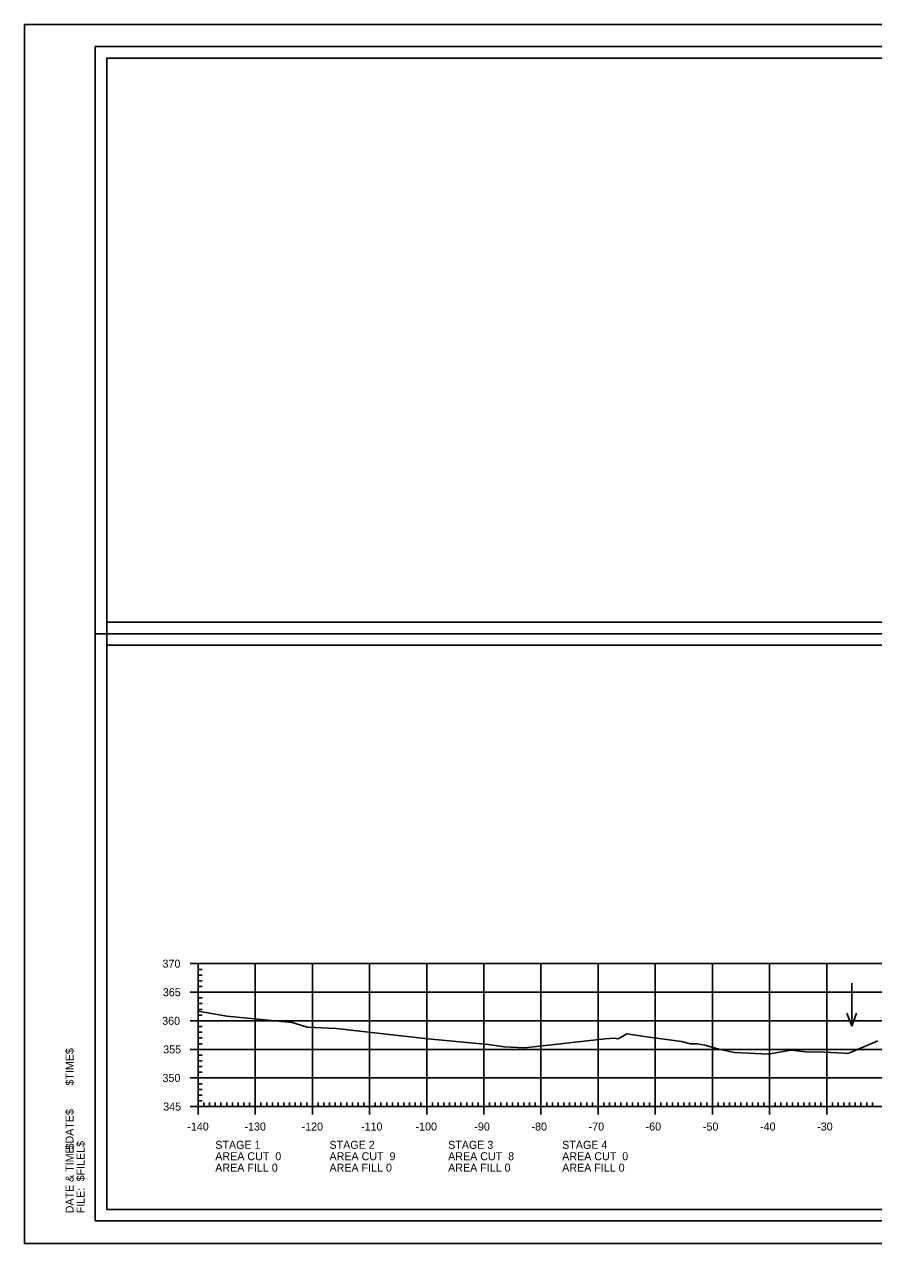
# Model space of a CAD drawing. Extents: x 1368910 to 1369601, y 380116 to 380950.
# Drawn here: x 1369267.2 to 1369415.8, y 380737.1 to 380950.5 of the extents above; entities that cross this region are included whole.
import ezdxf

# ---------------------------------------------------------------- set-up
doc = ezdxf.new("R2010")
doc.units = 0
for name, color, linetype in [('R_Axis', 7, 'Continuous'), ('R_Axis Annot', 7, 'Continuous'), ('R_Border', 7, 'Continuous'), ('R_Border Notes', 7, 'Continuous'), ('R_Border Plan-Plan', 7, 'Continuous'), ('R_Exist Surface', 7, 'Continuous'), ('R_Grid', 7, 'Continuous'), ('R_No Plot', 7, 'Continuous'), ('R_Water Annot', 7, 'Continuous')]:
    doc.layers.add(name, color=color, linetype=linetype)

msp = doc.modelspace()

# ---------------------------------------------------------------- linework, layer by layer
at = {"layer": 'R_Axis'}
for p, q in [((1369296.19, 380786.1), (1369298.99, 380786.1)), ((1369297.59, 380761.1), (1369297.59, 380786.1)), ((1369297.59, 380785.1), (1369298.29, 380785.1)), ((1369297.59, 380784.1), (1369298.29, 380784.1)), ((1369297.59, 380783.1), (1369298.29, 380783.1)), ((1369297.59, 380782.1), (1369298.29, 380782.1)), ((1369296.19, 380781.1), (1369298.99, 380781.1)), ((1369297.59, 380780.1), (1369298.29, 380780.1)), ((1369297.59, 380779.1), (1369298.29, 380779.1)), ((1369297.59, 380778.1), (1369298.29, 380778.1)), ((1369296.19, 380776.1), (1369298.99, 380776.1)), ((1369297.59, 380777.1), (1369298.29, 380777.1)), ((1369297.59, 380775.1), (1369298.29, 380775.1)), ((1369297.59, 380774.1), (1369298.29, 380774.1)), ((1369297.59, 380773.1), (1369298.29, 380773.1)), ((1369297.59, 380772.1), (1369298.29, 380772.1)), ((1369296.19, 380771.1), (1369298.99, 380771.1)), ((1369297.59, 380770.1), (1369298.29, 380770.1)), ((1369297.59, 380769.1), (1369298.29, 380769.1)), ((1369297.59, 380768.1), (1369298.29, 380768.1)), ((1369297.59, 380767.1), (1369298.29, 380767.1)), ((1369296.19, 380766.1), (1369298.99, 380766.1)), ((1369297.59, 380765.1), (1369298.29, 380765.1)), ((1369297.59, 380764.1), (1369298.29, 380764.1)), ((1369297.59, 380763.1), (1369298.29, 380763.1)), ((1369296.19, 380761.1), (1369298.99, 380761.1)), ((1369297.59, 380759.7), (1369297.59, 380762.5)), ((1369297.59, 380762.1), (1369298.29, 380762.1)), ((1369297.59, 380761.1), (1369577.59, 380761.1)), ((1369298.59, 380761.1), (1369298.59, 380761.8)), ((1369299.59, 380761.1), (1369299.59, 380761.8)), ((1369300.59, 380761.1), (1369300.59, 380761.8)), ((1369301.59, 380761.1), (1369301.59, 380761.8)), ((1369302.59, 380761.1), (1369302.59, 380761.8)), ((1369303.59, 380761.1), (1369303.59, 380761.8)), ((1369304.59, 380761.1), (1369304.59, 380761.8)), ((1369305.59, 380761.1), (1369305.59, 380761.8)), ((1369306.59, 380761.1), (1369306.59, 380761.8)), ((1369307.59, 380759.7), (1369307.59, 380762.5)), ((1369308.59, 380761.1), (1369308.59, 380761.8)), ((1369309.59, 380761.1), (1369309.59, 380761.8)), ((1369310.59, 380761.1), (1369310.59, 380761.8)), ((1369311.59, 380761.1), (1369311.59, 380761.8)), ((1369312.59, 380761.1), (1369312.59, 380761.8)), ((1369313.59, 380761.1), (1369313.59, 380761.8)), ((1369314.59, 380761.1), (1369314.59, 380761.8)), ((1369315.59, 380761.1), (1369315.59, 380761.8)), ((1369316.59, 380761.1), (1369316.59, 380761.8)), ((1369317.59, 380759.7), (1369317.59, 380762.5)), ((1369318.59, 380761.1), (1369318.59, 380761.8)), ((1369319.59, 380761.1), (1369319.59, 380761.8)), ((1369320.59, 380761.1), (1369320.59, 380761.8)), ((1369321.59, 380761.1), (1369321.59, 380761.8)), ((1369322.59, 380761.1), (1369322.59, 380761.8)), ((1369323.59, 380761.1), (1369323.59, 380761.8)), ((1369324.59, 380761.1), (1369324.59, 380761.8)), ((1369325.59, 380761.1), (1369325.59, 380761.8)), ((1369326.59, 380761.1), (1369326.59, 380761.8)), ((1369327.59, 380759.7), (1369327.59, 380762.5)), ((1369328.59, 380761.1), (1369328.59, 380761.8)), ((1369329.59, 380761.1), (1369329.59, 380761.8)), ((1369330.59, 380761.1), (1369330.59, 380761.8)), ((1369331.59, 380761.1), (1369331.59, 380761.8)), ((1369332.59, 380761.1), (1369332.59, 380761.8)), ((1369333.59, 380761.1), (1369333.59, 380761.8)), ((1369334.59, 380761.1), (1369334.59, 380761.8)), ((1369335.59, 380761.1), (1369335.59, 380761.8)), ((1369336.59, 380761.1), (1369336.59, 380761.8)), ((1369337.59, 380759.7), (1369337.59, 380762.5)), ((1369338.59, 380761.1), (1369338.59, 380761.8)), ((1369339.59, 380761.1), (1369339.59, 380761.8)), ((1369340.59, 380761.1), (1369340.59, 380761.8)), ((1369341.59, 380761.1), (1369341.59, 380761.8)), ((1369342.59, 380761.1), (1369342.59, 380761.8)), ((1369343.59, 380761.1), (1369343.59, 380761.8)), ((1369344.59, 380761.1), (1369344.59, 380761.8)), ((1369345.59, 380761.1), (1369345.59, 380761.8)), ((1369346.59, 380761.1), (1369346.59, 380761.8)), ((1369347.59, 380759.7), (1369347.59, 380762.5)), ((1369348.59, 380761.1), (1369348.59, 380761.8)), ((1369349.59, 380761.1), (1369349.59, 380761.8)), ((1369350.59, 380761.1), (1369350.59, 380761.8)), ((1369351.59, 380761.1), (1369351.59, 380761.8)), ((1369352.59, 380761.1), (1369352.59, 380761.8)), ((1369353.59, 380761.1), (1369353.59, 380761.8)), ((1369354.59, 380761.1), (1369354.59, 380761.8)), ((1369355.59, 380761.1), (1369355.59, 380761.8)), ((1369356.59, 380761.1), (1369356.59, 380761.8)), ((1369357.59, 380759.7), (1369357.59, 380762.5)), ((1369358.59, 380761.1), (1369358.59, 380761.8)), ((1369359.59, 380761.1), (1369359.59, 380761.8)), ((1369360.59, 380761.1), (1369360.59, 380761.8)), ((1369361.59, 380761.1), (1369361.59, 380761.8)), ((1369362.59, 380761.1), (1369362.59, 380761.8)), ((1369363.59, 380761.1), (1369363.59, 380761.8)), ((1369364.59, 380761.1), (1369364.59, 380761.8)), ((1369365.59, 380761.1), (1369365.59, 380761.8)), ((1369366.59, 380761.1), (1369366.59, 380761.8)), ((1369367.59, 380759.7), (1369367.59, 380762.5)), ((1369368.59, 380761.1), (1369368.59, 380761.8)), ((1369369.59, 380761.1), (1369369.59, 380761.8)), ((1369370.59, 380761.1), (1369370.59, 380761.8)), ((1369371.59, 380761.1), (1369371.59, 380761.8)), ((1369372.59, 380761.1), (1369372.59, 380761.8)), ((1369373.59, 380761.1), (1369373.59, 380761.8)), ((1369374.59, 380761.1), (1369374.59, 380761.8)), ((1369375.59, 380761.1), (1369375.59, 380761.8)), ((1369376.59, 380761.1), (1369376.59, 380761.8)), ((1369377.59, 380759.7), (1369377.59, 380762.5)), ((1369378.59, 380761.1), (1369378.59, 380761.8)), ((1369379.59, 380761.1), (1369379.59, 380761.8)), ((1369380.59, 380761.1), (1369380.59, 380761.8)), ((1369381.59, 380761.1), (1369381.59, 380761.8)), ((1369382.59, 380761.1), (1369382.59, 380761.8)), ((1369383.59, 380761.1), (1369383.59, 380761.8)), ((1369384.59, 380761.1), (1369384.59, 380761.8)), ((1369385.59, 380761.1), (1369385.59, 380761.8)), ((1369386.59, 380761.1), (1369386.59, 380761.8)), ((1369387.59, 380759.7), (1369387.59, 380762.5)), ((1369388.59, 380761.1), (1369388.59, 380761.8)), ((1369389.59, 380761.1), (1369389.59, 380761.8)), ((1369390.59, 380761.1), (1369390.59, 380761.8)), ((1369391.59, 380761.1), (1369391.59, 380761.8)), ((1369392.59, 380761.1), (1369392.59, 380761.8)), ((1369393.59, 380761.1), (1369393.59, 380761.8)), ((1369394.59, 380761.1), (1369394.59, 380761.8)), ((1369395.59, 380761.1), (1369395.59, 380761.8)), ((1369396.59, 380761.1), (1369396.59, 380761.8)), ((1369397.59, 380759.7), (1369397.59, 380762.5)), ((1369398.59, 380761.1), (1369398.59, 380761.8)), ((1369399.59, 380761.1), (1369399.59, 380761.8)), ((1369400.59, 380761.1), (1369400.59, 380761.8)), ((1369401.59, 380761.1), (1369401.59, 380761.8)), ((1369402.59, 380761.1), (1369402.59, 380761.8)), ((1369403.59, 380761.1), (1369403.59, 380761.8)), ((1369404.59, 380761.1), (1369404.59, 380761.8)), ((1369405.59, 380761.1), (1369405.59, 380761.8)), ((1369406.59, 380761.1), (1369406.59, 380761.8)), ((1369407.59, 380759.7), (1369407.59, 380762.5)), ((1369408.59, 380761.1), (1369408.59, 380761.8)), ((1369409.59, 380761.1), (1369409.59, 380761.8)), ((1369410.59, 380761.1), (1369410.59, 380761.8)), ((1369411.59, 380761.1), (1369411.59, 380761.8)), ((1369412.59, 380761.1), (1369412.59, 380761.8)), ((1369413.59, 380761.1), (1369413.59, 380761.8)), ((1369414.59, 380761.1), (1369414.59, 380761.8)), ((1369415.59, 380761.1), (1369415.59, 380761.8))]:
    msp.add_line(p, q, dxfattribs=at)
at = {"layer": 'R_Border'}
for p, q in [((1369279.59, 380946.56), (1369595.77, 380946.56)), ((1369279.59, 380741.1), (1369279.59, 380946.56)), ((1369279.59, 380741.1), (1369279.59, 380741.1)), ((1369595.77, 380741.1), (1369279.59, 380741.1))]:
    msp.add_line(p, q, dxfattribs=at)
at = {"layer": 'R_Border Plan-Plan'}
msp.add_line((1369279.59, 380843.83), (1369595.77, 380843.83), dxfattribs=at)
at = {"layer": 'R_Exist Surface'}
msp.add_lwpolyline([(1369297.59, 380777.77), (1369302.63, 380776.89), (1369314.03, 380775.79), (1369316.65, 380774.96), (1369321.74, 380774.76), (1369337.76, 380772.93), (1369348.36, 380771.96), (1369351.16, 380771.55), (1369354.72, 380771.4), (1369368.82, 380772.94), (1369370.39, 380773.07), (1369370.78, 380772.98), (1369371.07, 380772.97), (1369372.6, 380773.8), (1369376.12, 380773.27), (1369382.17, 380772.5), (1369383.74, 380772.08), (1369384.98, 380772.09), (1369386.28, 380771.81), (1369388.97, 380771.08), (1369391.47, 380770.57), (1369393.98, 380770.46), (1369397.36, 380770.27), (1369401.34, 380770.95), (1369404.49, 380770.62), (1369405.96, 380770.66), (1369410.64, 380770.42), (1369411.28, 380770.4), (1369412.14, 380770.75), (1369416.56, 380772.58)], dxfattribs=at)
at = {"layer": 'R_Grid'}
for p, q in [((1369297.59, 380786.1), (1369577.59, 380786.1)), ((1369297.59, 380761.1), (1369297.59, 380786.1)), ((1369307.59, 380761.1), (1369307.59, 380786.1)), ((1369317.59, 380761.1), (1369317.59, 380786.1)), ((1369327.59, 380761.1), (1369327.59, 380786.1)), ((1369337.59, 380761.1), (1369337.59, 380786.1)), ((1369347.59, 380761.1), (1369347.59, 380786.1)), ((1369357.59, 380761.1), (1369357.59, 380786.1)), ((1369367.59, 380761.1), (1369367.59, 380786.1)), ((1369377.59, 380761.1), (1369377.59, 380786.1)), ((1369387.59, 380761.1), (1369387.59, 380786.1)), ((1369397.59, 380761.1), (1369397.59, 380786.1)), ((1369407.59, 380761.1), (1369407.59, 380786.1)), ((1369297.59, 380781.1), (1369577.59, 380781.1)), ((1369297.59, 380776.1), (1369577.59, 380776.1)), ((1369297.59, 380771.1), (1369577.59, 380771.1)), ((1369297.59, 380766.1), (1369577.59, 380766.1)), ((1369297.59, 380761.1), (1369577.59, 380761.1))]:
    msp.add_line(p, q, dxfattribs=at)
at = {"layer": 'R_No Plot'}
for points in [[(1369267.18, 380950.45), (1369600.52, 380950.45), (1369600.52, 380737.11), (1369267.18, 380737.11)], [(1369593.77, 380845.83), (1369281.59, 380845.83), (1369281.59, 380944.56), (1369531.13, 380944.56), (1369531.13, 380934.68), (1369548.67, 380934.68), (1369572.77, 380934.68), (1369572.77, 380912.34), (1369593.77, 380912.34)], [(1369281.59, 380944.56), (1369531.13, 380944.56), (1369531.13, 380934.68), (1369548.67, 380934.68), (1369572.77, 380934.68), (1369572.77, 380912.34), (1369593.77, 380912.34), (1369593.77, 380743.1), (1369281.59, 380743.1)], [(1369281.59, 380841.83), (1369593.77, 380841.83), (1369593.77, 380743.1), (1369281.59, 380743.1)]]:
    msp.add_lwpolyline(points, close=True, dxfattribs=at)
at = {"layer": 'R_Water Annot'}
for p, q in [((1369411.98, 380782.69), (1369411.98, 380775.15)), ((1369411.98, 380775.15), (1369411.14, 380777.46)), ((1369411.98, 380775.15), (1369412.82, 380777.46))]:
    msp.add_line(p, q, dxfattribs=at)

# ---------------------------------------------------------------- texts
at = {"layer": 'R_Axis Annot'}
for s, p in [('370', (1369291.36, 380785.4)), ('365', (1369291.42, 380780.4)), ('360', (1369291.3, 380775.4)), ('355', (1369291.48, 380770.4)), ('350', (1369291.36, 380765.4)), ('345', (1369291.48, 380760.4)), ('-140', (1369295.7, 380756.9)), ('-130', (1369305.7, 380756.9)), ('-120', (1369315.7, 380756.9)), ('-110', (1369326.1, 380756.9)), ('-100', (1369335.64, 380756.9)), ('-90', (1369345.93, 380756.9)), ('-80', (1369355.93, 380756.9)), ('-70', (1369365.93, 380756.9)), ('-60', (1369375.9, 380756.9)), ('-50', (1369385.93, 380756.9)), ('-40', (1369395.93, 380756.9)), ('-30', (1369405.93, 380756.9)), ('STAGE 1', (1369300.59, 380753.7)), ('STAGE 2', (1369320.58, 380753.7)), ('STAGE 3', (1369341.34, 380753.7)), ('STAGE 4', (1369361.3, 380753.7)), ('AREA CUT  0', (1369300.59, 380751.7)), ('AREA CUT  9', (1369320.58, 380751.7)), ('AREA CUT  8', (1369341.34, 380751.7)), ('AREA CUT  0', (1369361.3, 380751.7)), ('AREA FILL 0', (1369300.59, 380749.7)), ('AREA FILL 0', (1369320.58, 380749.7)), ('AREA FILL 0', (1369341.34, 380749.7)), ('AREA FILL 0', (1369361.3, 380749.7))]:
    msp.add_text(s, height=1.4, dxfattribs=at).set_placement(p)
at = {"layer": 'R_Border Notes'}
for s, height, p in [('$TIME$', 1.397, (1369275.79, 380764.77)), ('$DATE$', 1.397, (1369275.79, 380753.59)), ('DATE & TIME:', 1.3968, (1369275.79, 380742.42)), ('$FILEL$', 1.397, (1369277.71, 380748.01)), ('FILE: ', 1.397, (1369277.71, 380742.42))]:
    msp.add_text(s, height=height, rotation=90, dxfattribs=at).set_placement(p)

doc.saveas('drawing.dxf')
